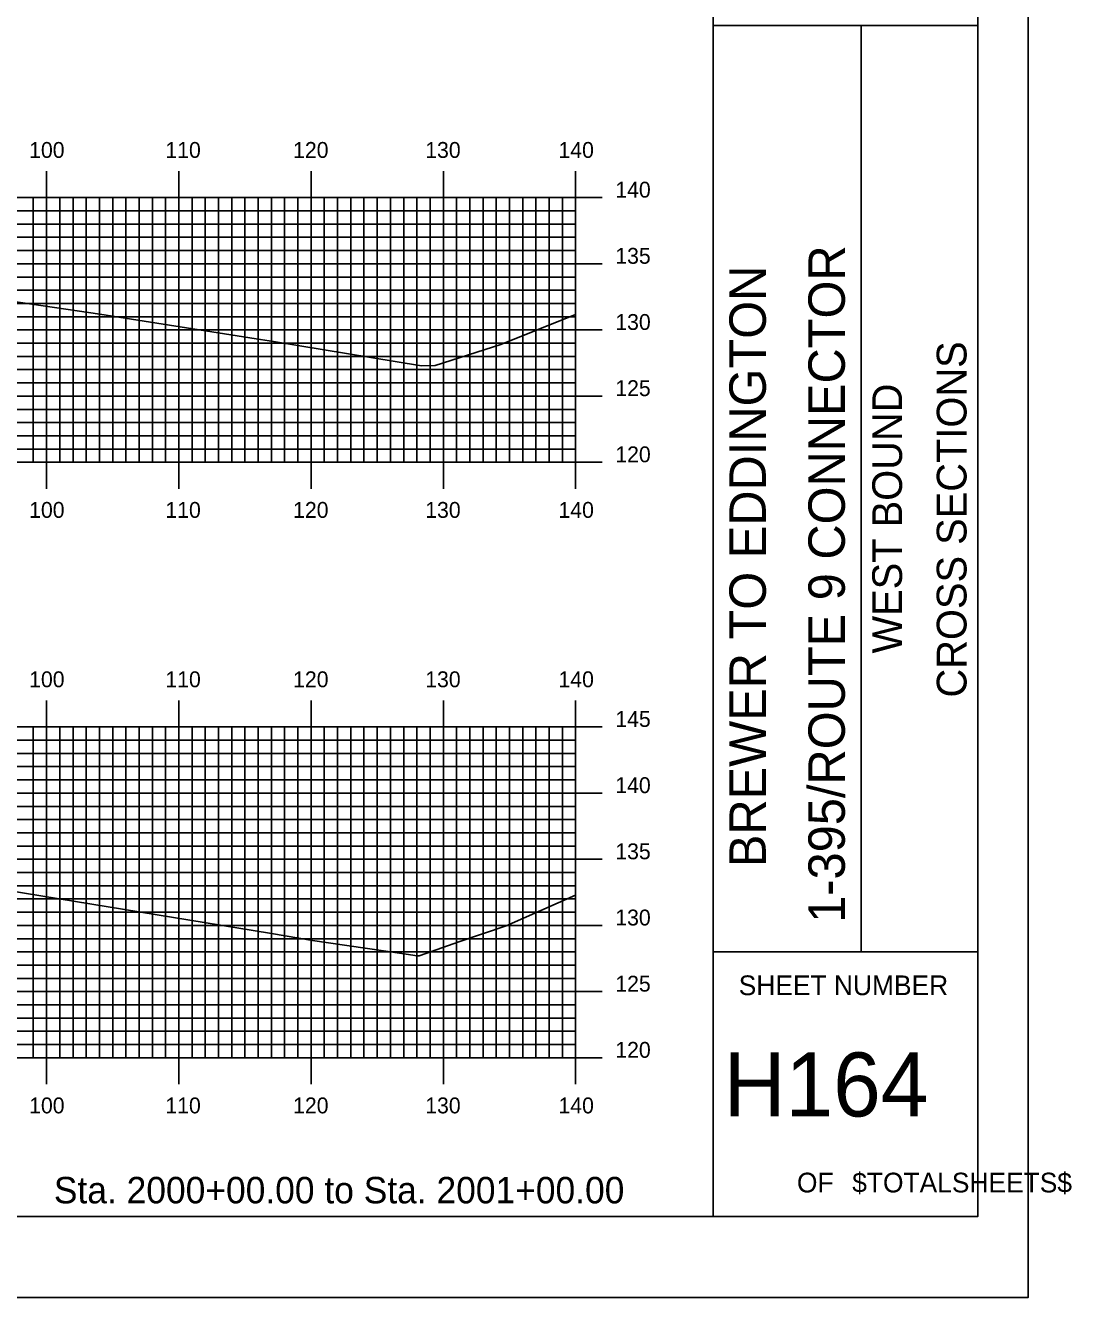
# Model space of a CAD drawing. Extents: x 850746 to 851089, y 366605 to 366825.
# Drawn here: x 851009.8 to 851088.9, y 366604.9 to 366701.1 of the extents above; entities that cross this region are included whole.
import ezdxf

# ---------------------------------------------------------------- set-up
doc = ezdxf.new("R2010")
doc.units = 0
for name, color, linetype in [('BORDER', 7, 'Continuous'), ('H_V ANNOTATION', 7, 'Continuous'), ('MAJOR', 7, 'Continuous'), ('MINOR', 7, 'Continuous'), ('PLOT BOUNDARY', 7, 'Continuous'), ('S_Roadway_Centerline', 7, 'Continuous')]:
    doc.layers.add(name, color=color, linetype=linetype)

msp = doc.modelspace()

# ---------------------------------------------------------------- linework, layer by layer
at = {"layer": 'BORDER'}
for p, q in [((851061.825, 366611.055), (851061.825, 366821.055)), ((851061.825, 366701.061), (851081.825, 366701.061)), ((851073.007, 366631.061), (851073.007, 366701.061)), ((851061.825, 366631.061), (851081.825, 366631.061))]:
    msp.add_line(p, q, dxfattribs=at)
msp.add_lwpolyline([(850761.825, 366611.055), (851081.825, 366611.055), (851081.825, 366821.055), (850761.825, 366821.055)], close=True, dxfattribs=at)
at = {"layer": 'MAJOR'}
for p, q in [((851011.425, 366690.059), (851011.425, 366688.055)), ((851021.425, 366690.059), (851021.425, 366688.055)), ((851031.425, 366690.059), (851031.425, 366688.055)), ((851041.425, 366690.059), (851041.425, 366688.055)), ((851051.425, 366690.059), (851051.425, 366688.055)), ((850771.425, 366688.055), (851051.425, 366688.055)), ((850771.425, 366688.055), (851051.425, 366688.055)), ((851011.425, 366668.055), (851011.425, 366688.055)), ((851021.425, 366668.055), (851021.425, 366688.055)), ((851031.425, 366668.055), (851031.425, 366688.055)), ((851041.425, 366668.055), (851041.425, 366688.055)), ((851053.429, 366688.055), (851049.421, 366688.055)), ((851051.425, 366668.055), (851051.425, 366688.055)), ((851051.425, 366668.055), (851051.425, 366688.055)), ((850771.425, 366683.055), (851051.425, 366683.055)), ((851053.429, 366683.055), (851049.421, 366683.055)), ((850771.425, 366678.055), (851051.425, 366678.055)), ((851053.429, 366678.055), (851049.421, 366678.055)), ((850771.425, 366673.055), (851051.425, 366673.055)), ((851053.429, 366673.055), (851049.421, 366673.055)), ((850771.425, 366668.055), (851051.425, 366668.055)), ((850771.425, 366668.055), (851051.425, 366668.055)), ((851011.425, 366666.051), (851011.425, 366668.055)), ((851021.425, 366666.051), (851021.425, 366668.055)), ((851031.425, 366666.051), (851031.425, 366668.055)), ((851041.425, 366666.051), (851041.425, 366668.055)), ((851053.429, 366668.055), (851049.421, 366668.055)), ((851051.425, 366666.051), (851051.425, 366668.055)), ((851011.425, 366650.059), (851011.425, 366648.055)), ((851021.425, 366650.059), (851021.425, 366648.055)), ((851031.425, 366650.059), (851031.425, 366648.055)), ((851041.425, 366650.059), (851041.425, 366648.055)), ((851051.425, 366650.059), (851051.425, 366648.055)), ((850771.425, 366648.055), (851051.425, 366648.055)), ((850771.425, 366648.055), (851051.425, 366648.055)), ((851011.425, 366623.055), (851011.425, 366648.055)), ((851021.425, 366623.055), (851021.425, 366648.055)), ((851031.425, 366623.055), (851031.425, 366648.055)), ((851041.425, 366623.055), (851041.425, 366648.055)), ((851053.429, 366648.055), (851049.421, 366648.055)), ((851051.425, 366623.055), (851051.425, 366648.055)), ((851051.425, 366623.055), (851051.425, 366648.055)), ((850771.425, 366643.055), (851051.425, 366643.055)), ((851053.429, 366643.055), (851049.421, 366643.055)), ((850771.425, 366638.055), (851051.425, 366638.055)), ((851053.429, 366638.055), (851049.421, 366638.055)), ((850771.425, 366633.055), (851051.425, 366633.055)), ((851053.429, 366633.055), (851049.421, 366633.055)), ((850771.425, 366628.055), (851051.425, 366628.055)), ((851053.429, 366628.055), (851049.421, 366628.055)), ((850771.425, 366623.055), (851051.425, 366623.055)), ((850771.425, 366623.055), (851051.425, 366623.055)), ((851011.425, 366621.051), (851011.425, 366623.055)), ((851021.425, 366621.051), (851021.425, 366623.055)), ((851031.425, 366621.051), (851031.425, 366623.055)), ((851041.425, 366621.051), (851041.425, 366623.055)), ((851053.429, 366623.055), (851049.421, 366623.055)), ((851051.425, 366621.051), (851051.425, 366623.055))]:
    msp.add_line(p, q, dxfattribs=at)
at = {"layer": 'MINOR'}
for p, q in [((851010.425, 366668.055), (851010.425, 366688.055)), ((851012.425, 366668.055), (851012.425, 366688.055)), ((851013.425, 366668.055), (851013.425, 366688.055)), ((851014.425, 366668.055), (851014.425, 366688.055)), ((851015.425, 366668.055), (851015.425, 366688.055)), ((851016.425, 366668.055), (851016.425, 366688.055)), ((851017.425, 366668.055), (851017.425, 366688.055)), ((851018.425, 366668.055), (851018.425, 366688.055)), ((851019.425, 366668.055), (851019.425, 366688.055)), ((851020.425, 366668.055), (851020.425, 366688.055)), ((851022.425, 366668.055), (851022.425, 366688.055)), ((851023.425, 366668.055), (851023.425, 366688.055)), ((851024.425, 366668.055), (851024.425, 366688.055)), ((851025.425, 366668.055), (851025.425, 366688.055)), ((851026.425, 366668.055), (851026.425, 366688.055)), ((851027.425, 366668.055), (851027.425, 366688.055)), ((851028.425, 366668.055), (851028.425, 366688.055)), ((851029.425, 366668.055), (851029.425, 366688.055)), ((851030.425, 366668.055), (851030.425, 366688.055)), ((851032.425, 366668.055), (851032.425, 366688.055)), ((851033.425, 366668.055), (851033.425, 366688.055)), ((851034.425, 366668.055), (851034.425, 366688.055)), ((851035.425, 366668.055), (851035.425, 366688.055)), ((851036.425, 366668.055), (851036.425, 366688.055)), ((851037.425, 366668.055), (851037.425, 366688.055)), ((851038.425, 366668.055), (851038.425, 366688.055)), ((851039.425, 366668.055), (851039.425, 366688.055)), ((851040.425, 366668.055), (851040.425, 366688.055)), ((851042.425, 366668.055), (851042.425, 366688.055)), ((851043.425, 366668.055), (851043.425, 366688.055)), ((851044.425, 366668.055), (851044.425, 366688.055)), ((851045.425, 366668.055), (851045.425, 366688.055)), ((851046.425, 366668.055), (851046.425, 366688.055)), ((851047.425, 366668.055), (851047.425, 366688.055)), ((851048.425, 366668.055), (851048.425, 366688.055)), ((851049.425, 366668.055), (851049.425, 366688.055)), ((851050.425, 366668.055), (851050.425, 366688.055)), ((850771.425, 366687.055), (851051.425, 366687.055)), ((851051.425, 366687.055), (851049.421, 366687.055)), ((850771.425, 366686.055), (851051.425, 366686.055)), ((851051.425, 366686.055), (851049.421, 366686.055)), ((850771.425, 366685.055), (851051.425, 366685.055)), ((851051.425, 366685.055), (851049.421, 366685.055)), ((850771.425, 366684.055), (851051.425, 366684.055)), ((851051.425, 366684.055), (851049.421, 366684.055)), ((850771.425, 366682.055), (851051.425, 366682.055)), ((851051.425, 366682.055), (851049.421, 366682.055)), ((850771.425, 366681.055), (851051.425, 366681.055)), ((851051.425, 366681.055), (851049.421, 366681.055)), ((850771.425, 366680.055), (851051.425, 366680.055)), ((851051.425, 366680.055), (851049.421, 366680.055)), ((850771.425, 366679.055), (851051.425, 366679.055)), ((851051.425, 366679.055), (851049.421, 366679.055)), ((850771.425, 366677.055), (851051.425, 366677.055)), ((851051.425, 366677.055), (851049.421, 366677.055)), ((850771.425, 366676.055), (851051.425, 366676.055)), ((851051.425, 366676.055), (851049.421, 366676.055)), ((850771.425, 366675.055), (851051.425, 366675.055)), ((851051.425, 366675.055), (851049.421, 366675.055)), ((850771.425, 366674.055), (851051.425, 366674.055)), ((851051.425, 366674.055), (851049.421, 366674.055)), ((850771.425, 366672.055), (851051.425, 366672.055)), ((851051.425, 366672.055), (851049.421, 366672.055)), ((850771.425, 366671.055), (851051.425, 366671.055)), ((851051.425, 366671.055), (851049.421, 366671.055)), ((850771.425, 366670.055), (851051.425, 366670.055)), ((851051.425, 366670.055), (851049.421, 366670.055)), ((850771.425, 366669.055), (851051.425, 366669.055)), ((851051.425, 366669.055), (851049.421, 366669.055)), ((851010.425, 366623.055), (851010.425, 366648.055)), ((851012.425, 366623.055), (851012.425, 366648.055)), ((851013.425, 366623.055), (851013.425, 366648.055)), ((851014.425, 366623.055), (851014.425, 366648.055)), ((851015.425, 366623.055), (851015.425, 366648.055)), ((851016.425, 366623.055), (851016.425, 366648.055)), ((851017.425, 366623.055), (851017.425, 366648.055)), ((851018.425, 366623.055), (851018.425, 366648.055)), ((851019.425, 366623.055), (851019.425, 366648.055)), ((851020.425, 366623.055), (851020.425, 366648.055)), ((851022.425, 366623.055), (851022.425, 366648.055)), ((851023.425, 366623.055), (851023.425, 366648.055)), ((851024.425, 366623.055), (851024.425, 366648.055)), ((851025.425, 366623.055), (851025.425, 366648.055)), ((851026.425, 366623.055), (851026.425, 366648.055)), ((851027.425, 366623.055), (851027.425, 366648.055)), ((851028.425, 366623.055), (851028.425, 366648.055)), ((851029.425, 366623.055), (851029.425, 366648.055)), ((851030.425, 366623.055), (851030.425, 366648.055)), ((851032.425, 366623.055), (851032.425, 366648.055)), ((851033.425, 366623.055), (851033.425, 366648.055)), ((851034.425, 366623.055), (851034.425, 366648.055)), ((851035.425, 366623.055), (851035.425, 366648.055)), ((851036.425, 366623.055), (851036.425, 366648.055)), ((851037.425, 366623.055), (851037.425, 366648.055)), ((851038.425, 366623.055), (851038.425, 366648.055)), ((851039.425, 366623.055), (851039.425, 366648.055)), ((851040.425, 366623.055), (851040.425, 366648.055)), ((851042.425, 366623.055), (851042.425, 366648.055)), ((851043.425, 366623.055), (851043.425, 366648.055)), ((851044.425, 366623.055), (851044.425, 366648.055)), ((851045.425, 366623.055), (851045.425, 366648.055)), ((851046.425, 366623.055), (851046.425, 366648.055)), ((851047.425, 366623.055), (851047.425, 366648.055)), ((851048.425, 366623.055), (851048.425, 366648.055)), ((851049.425, 366623.055), (851049.425, 366648.055)), ((851050.425, 366623.055), (851050.425, 366648.055)), ((850771.425, 366647.055), (851051.425, 366647.055)), ((851051.425, 366647.055), (851049.421, 366647.055)), ((850771.425, 366646.055), (851051.425, 366646.055)), ((851051.425, 366646.055), (851049.421, 366646.055)), ((850771.425, 366645.055), (851051.425, 366645.055)), ((851051.425, 366645.055), (851049.421, 366645.055)), ((850771.425, 366644.055), (851051.425, 366644.055)), ((851051.425, 366644.055), (851049.421, 366644.055)), ((850771.425, 366642.055), (851051.425, 366642.055)), ((851051.425, 366642.055), (851049.421, 366642.055)), ((850771.425, 366641.055), (851051.425, 366641.055)), ((851051.425, 366641.055), (851049.421, 366641.055)), ((850771.425, 366640.055), (851051.425, 366640.055)), ((851051.425, 366640.055), (851049.421, 366640.055)), ((850771.425, 366639.055), (851051.425, 366639.055)), ((851051.425, 366639.055), (851049.421, 366639.055)), ((850771.425, 366637.055), (851051.425, 366637.055)), ((851051.425, 366637.055), (851049.421, 366637.055)), ((850771.425, 366636.055), (851051.425, 366636.055)), ((851051.425, 366636.055), (851049.421, 366636.055)), ((850771.425, 366635.055), (851051.425, 366635.055)), ((851051.425, 366635.055), (851049.421, 366635.055)), ((850771.425, 366634.055), (851051.425, 366634.055)), ((851051.425, 366634.055), (851049.421, 366634.055)), ((850771.425, 366632.055), (851051.425, 366632.055)), ((851051.425, 366632.055), (851049.421, 366632.055)), ((850771.425, 366631.055), (851051.425, 366631.055)), ((851051.425, 366631.055), (851049.421, 366631.055)), ((850771.425, 366630.055), (851051.425, 366630.055)), ((851051.425, 366630.055), (851049.421, 366630.055)), ((850771.425, 366629.055), (851051.425, 366629.055)), ((851051.425, 366629.055), (851049.421, 366629.055)), ((850771.425, 366627.055), (851051.425, 366627.055)), ((851051.425, 366627.055), (851049.421, 366627.055)), ((850771.425, 366626.055), (851051.425, 366626.055)), ((851051.425, 366626.055), (851049.421, 366626.055)), ((850771.425, 366625.055), (851051.425, 366625.055)), ((851051.425, 366625.055), (851049.421, 366625.055)), ((850771.425, 366624.055), (851051.425, 366624.055)), ((851051.425, 366624.055), (851049.421, 366624.055))]:
    msp.add_line(p, q, dxfattribs=at)
at = {"layer": 'PLOT BOUNDARY'}
msp.add_lwpolyline([(850745.639, 366604.937), (851085.639, 366604.937), (851085.639, 366824.937), (850745.639, 366824.937)], close=True, dxfattribs=at)
at = {"layer": 'S_Roadway_Centerline'}
for points in [[(851005.313, 366680.726), (851010.319, 366679.99), (851015.46, 366679.239), (851027.263, 366677.386), (851028.571, 366677.183), (851039.783, 366675.344), (851040.8, 366675.356), (851045.77, 366676.947), (851051.425, 366679.233)], [(851008.526, 366635.694), (851028.424, 366632.438), (851031.534, 366631.916), (851038.292, 366630.932), (851039.433, 366630.762), (851039.605, 366630.771), (851042.676, 366631.831), (851046.184, 366633.034), (851051.425, 366635.344)]]:
    msp.add_lwpolyline(points, dxfattribs=at)

# ---------------------------------------------------------------- texts
at = {"layer": 'BORDER'}
for s, height, p in [('1-395/ROUTE 9 CONNECTOR', 2.75575, (851071.78, 366633.255)), ('BREWER TO EDDINGTON', 2.75575, (851065.809, 366637.464)), ('CROSS SECTIONS', 2.25, (851080.979, 366650.277)), ('WEST BOUND', 2.25, (851076.104, 366653.608))]:
    msp.add_text(s, height=height, rotation=90, dxfattribs=at).set_placement(p)
for s, height, p in [('SHEET NUMBER', 1.49054, (851063.756, 366627.788)), ('H164', 4.8388, (851062.627, 366618.62)), ('OF', 1.4905, (851068.159, 366612.881)), ('$TOTALSHEETS$', 1.49054, (851072.338, 366612.881))]:
    msp.add_text(s, height=height, dxfattribs=at).set_placement(p)
at = {"layer": 'H_V ANNOTATION'}
for s, height, p in [('100', 1.2, (851010.109, 366691.055)), ('110', 1.2, (851020.409, 366691.055)), ('120', 1.2, (851030.066, 366691.055)), ('130', 1.2, (851040.055, 366691.055)), ('140', 1.2, (851050.13, 366691.055)), ('140', 1.2, (851054.425, 366688.055)), ('135', 1.2, (851054.425, 366683.055)), ('130', 1.2, (851054.425, 366678.055)), ('125', 1.2, (851054.425, 366673.055)), ('120', 1.2, (851054.425, 366668.055)), ('100', 1.2, (851010.109, 366663.855)), ('110', 1.2, (851020.409, 366663.855)), ('120', 1.2, (851030.066, 366663.855)), ('130', 1.2, (851040.055, 366663.855)), ('140', 1.2, (851050.13, 366663.855)), ('100', 1.2, (851010.109, 366651.055)), ('110', 1.2, (851020.409, 366651.055)), ('120', 1.2, (851030.066, 366651.055)), ('130', 1.2, (851040.055, 366651.055)), ('140', 1.2, (851050.13, 366651.055)), ('145', 1.2, (851054.425, 366648.055)), ('140', 1.2, (851054.425, 366643.055)), ('135', 1.2, (851054.425, 366638.055)), ('130', 1.2, (851054.425, 366633.055)), ('125', 1.2, (851054.425, 366628.055)), ('120', 1.2, (851054.425, 366623.055)), ('100', 1.2, (851010.109, 366618.855)), ('110', 1.2, (851020.409, 366618.855)), ('120', 1.2, (851030.066, 366618.855)), ('130', 1.2, (851040.055, 366618.855)), ('140', 1.2, (851050.13, 366618.855)), ('Sta. 2000+00.00 to Sta. 2001+00.00', 2.0004, (851011.978, 366612.055))]:
    msp.add_text(s, height=height, dxfattribs=at).set_placement(p)

doc.saveas('drawing.dxf')
